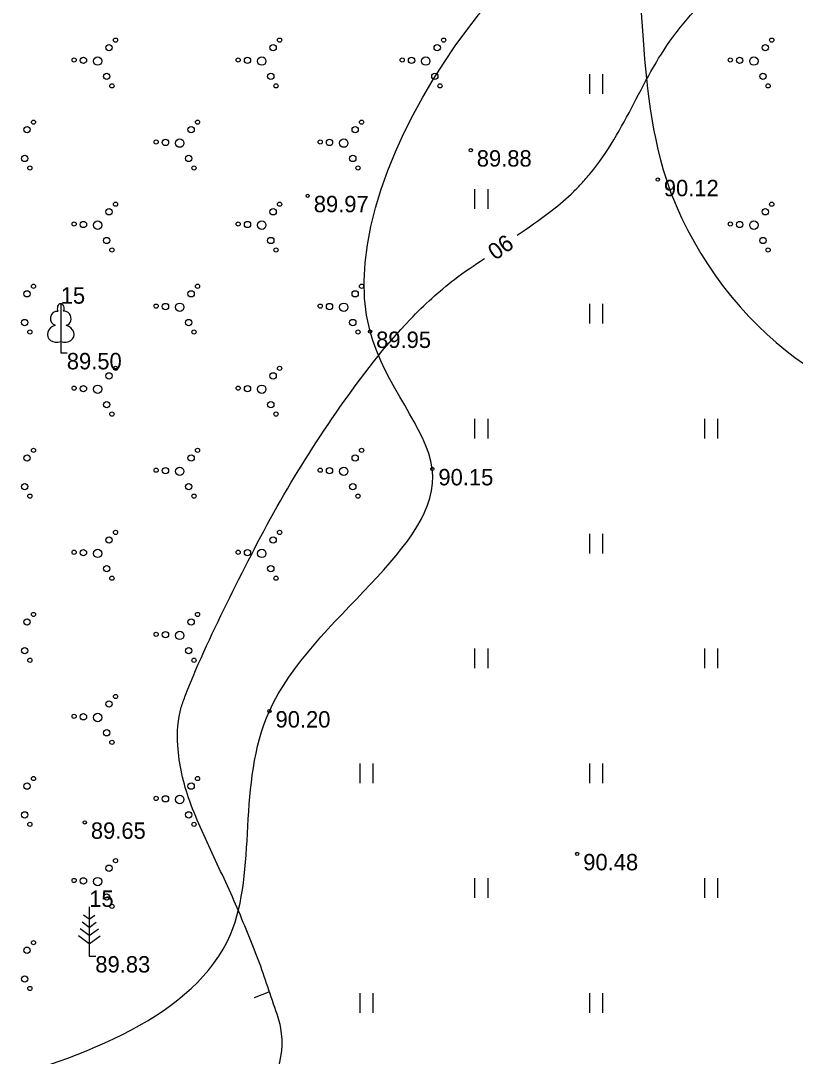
# Model space of a CAD drawing. Extents: x 635228 to 635525, y 248590 to 248800.
# Drawn here: x 635355.15 to 635378.76, y 248677.18 to 248708.73 of the extents above; entities that cross this region are included whole.
import ezdxf

# ---------------------------------------------------------------- set-up
doc = ezdxf.new("R2010")
doc.units = 0
for name, color, linetype in [('RELJ_AATZ_####_TKST_#', 7, 'Continuous'), ('RELJ_ELEM_####_####_#', 7, 'Continuous'), ('RELJ_HORZ_####_TKST_#', 7, 'Continuous'), ('RELJ_HORZ_PAMT_####_#', 7, 'Continuous'), ('RELJ_HORZ_RESN_####_#', 7, 'Continuous'), ('RELJ_NOGA_####_####_#', 7, 'Continuous'), ('RELJ_NOGL_####_####_#', 7, 'Continuous'), ('TERT_DIAM_####_TKST_#', 7, 'Continuous'), ('TERT_ELEM_####_####_#', 7, 'Continuous'), ('TERT_KONT_####_####_#', 7, 'Continuous')]:
    doc.layers.add(name, color=color, linetype=linetype)

msp = doc.modelspace()

# ---------------------------------------------------------------- linework, layer by layer
at = {"layer": 'RELJ_ELEM_####_####_#'}
for centre in [(635368.869, 248704.785), (635374.571, 248703.89), (635363.901, 248703.394), (635365.801, 248699.259), (635367.699, 248695.072), (635362.735, 248687.694), (635357.107, 248684.303), (635372.114, 248683.343)]:
    msp.add_circle(centre, 0.05, dxfattribs=at)
at = {"layer": 'RELJ_HORZ_PAMT_####_#'}
msp.add_spline([(635330.297, 248677.354), (635331.177, 248678.319), (635332.06, 248679.489), (635332.793, 248680.772), (635333.481, 248682.089), (635334.226, 248683.36), (635335.284, 248684.77), (635336.431, 248686.125), (635337.538, 248687.508), (635338.035, 248688.237), (635338.472, 248689.004), (635339.583, 248691.554), (635340.487, 248694.188), (635341.335, 248696.84), (635341.787, 248698.153), (635342.281, 248699.447), (635343.206, 248701.423), (635344.222, 248703.369), (635345.157, 248705.345), (635345.54, 248706.364), (635345.837, 248707.412), (635346.445, 248710.352), (635346.944, 248713.307), (635347.835, 248719.233), (635348.116, 248721.113), (635348.378, 248722.995), (635348.645, 248724.878), (635348.937, 248726.758), (635349.503, 248728.159), (635350.332, 248729.539), (635351.235, 248730.852), (635351.672, 248731.412), (635352.153, 248731.934), (635352.67, 248732.415), (635353.216, 248732.849), (635353.585, 248732.808), (635353.973, 248732.393), (635354.375, 248731.871), (635354.581, 248731.654), (635354.79, 248731.511), (635355.514, 248731.162), (635356.357, 248730.815), (635357.156, 248730.69), (635357.748, 248731.008), (635358.207, 248731.666), (635358.657, 248732.33), (635359.531, 248733.675), (635361.193, 248736.42), (635362.771, 248739.216), (635364.301, 248742.038), (635372.089, 248756.526)], degree=3, dxfattribs=at)
at = {"layer": 'RELJ_HORZ_RESN_####_#'}
msp.add_line((635362.735, 248679.142), (635362.27, 248678.96), dxfattribs=at)
for points in [[(635370.286, 248702.191), (635371.268, 248702.893), (635371.931, 248703.448), (635372.235, 248703.758), (635372.523, 248704.086), (635373.233, 248705.103), (635373.842, 248706.207), (635374.44, 248707.318), (635375.119, 248708.351), (635375.519, 248708.837), (635375.945, 248709.297), (635376.871, 248710.138), (635378.872, 248711.708), (635380.875, 248713.355), (635381.799, 248714.3), (635382.631, 248715.376), (635384.271, 248718.308), (635385.412, 248721.331), (635386.184, 248724.417), (635386.472, 248725.973), (635386.718, 248727.534), (635386.765, 248728.402), (635386.702, 248729.274), (635386.549, 248730.144), (635386.323, 248731.007), (635386.319, 248731.019)], [(635342.967, 248665.189), (635350.649, 248671.097), (635353.044, 248672.199), (635354.147, 248672.641), (635355.27, 248673.022), (635357.544, 248673.711), (635360.916, 248674.993), (635361.461, 248675.281), (635362, 248675.6), (635362.585, 248676.091), (635362.941, 248676.666), (635363.082, 248678.034), (635362.825, 248678.873), (635362.542, 248679.71), (635361.896, 248681.359), (635361.504, 248682.258), (635361.094, 248683.142), (635360.687, 248684.033), (635360.306, 248684.949), (635359.942, 248686.647), (635360.049, 248687.813), (635360.176, 248688.176), (635361.529, 248691.159), (635363.072, 248694.104), (635364.881, 248696.95), (635367.032, 248699.635), (635368.378, 248700.848), (635369.286, 248701.486)]]:
    msp.add_spline(points, degree=3, dxfattribs=at)
at = {"layer": 'RELJ_NOGA_####_####_#'}
for points in [[(635375.27, 248754.857), (635369.314, 248744.971), (635367.429, 248741.507), (635365.696, 248737.957), (635363.943, 248734.417), (635363.006, 248732.681), (635362, 248730.984), (635361.355, 248730.103), (635360.628, 248729.283), (635359.885, 248728.474), (635359.193, 248727.625), (635357.58, 248725.368), (635356.018, 248723.079), (635353.089, 248718.349), (635349.569, 248710.638), (635349.163, 248709.221), (635348.864, 248707.772), (635348.539, 248706.335), (635348.053, 248704.954), (635343.12, 248694.162), (635337.407, 248681.667), (635331.093, 248670.147), (635326.8, 248663.851)], [(635326.8, 248663.851), (635325.31, 248661.345), (635325.174, 248660.918), (635325.219, 248660.451), (635325.416, 248659.984), (635325.736, 248659.553), (635326.126, 248659.27), (635326.575, 248659.146), (635327.409, 248659.333), (635327.907, 248659.688), (635328.397, 248660.078), (635328.864, 248660.506), (635329.288, 248660.978), (635331.594, 248663.918), (635332.687, 248665.412), (635333.734, 248666.95), (635337.875, 248673.353), (635341.554, 248680.001), (635347.428, 248693.006), (635353.063, 248706.101), (635354.098, 248708.621), (635355.097, 248711.155), (635356.117, 248713.682), (635356.653, 248714.935), (635357.216, 248716.179), (635358.916, 248719.218), (635360.822, 248722.14), (635362.339, 248724.363), (635363.916, 248726.545), (635365.467, 248728.744), (635366.906, 248731.015), (635368.464, 248733.981), (635369.863, 248737.03), (635371.249, 248740.086), (635372.769, 248743.072), (635378.435, 248753.196)]]:
    msp.add_spline(points, degree=3, dxfattribs=at)
at = {"layer": 'RELJ_NOGL_####_####_#'}
msp.add_spline([(635326.936, 248660.713), (635331.766, 248667.928), (635333.88, 248671.254), (635335.853, 248674.668), (635337.706, 248678.153), (635339.464, 248681.691), (635342.12, 248687.391), (635344.65, 248693.14), (635347.108, 248698.916), (635349.548, 248704.698), (635350.777, 248707.84), (635351.91, 248711.022), (635353.067, 248714.195), (635353.692, 248715.764), (635354.368, 248717.312), (635355.034, 248718.536), (635355.835, 248719.677), (635357.677, 248721.811), (635359.567, 248723.919), (635361.176, 248726.206), (635362.355, 248728.434), (635362.939, 248729.551), (635363.546, 248730.656), (635367.422, 248737.348), (635371.307, 248744.035), (635372.506, 248746.487), (635373.579, 248749.023), (635374.785, 248751.459), (635376.384, 248753.612), (635376.807, 248754.05)], degree=3, dxfattribs=at)
at = {"layer": 'TERT_ELEM_####_####_#'}
for p, q in [((635372.5, 248706.5), (635372.5, 248707.1)), ((635372.9, 248706.5), (635372.9, 248707.1)), ((635369, 248703), (635369, 248703.6)), ((635369.4, 248703), (635369.4, 248703.6)), ((635372.5, 248699.5), (635372.5, 248700.1)), ((635372.9, 248699.5), (635372.9, 248700.1)), ((635356.374, 248698.954), (635356.374, 248698.607)), ((635356.374, 248698.607), (635356.574, 248698.607)), ((635369, 248696), (635369, 248696.6)), ((635369.4, 248696), (635369.4, 248696.6)), ((635376, 248696), (635376, 248696.6)), ((635376.4, 248696), (635376.4, 248696.6)), ((635372.5, 248692.5), (635372.5, 248693.1)), ((635372.9, 248692.5), (635372.9, 248693.1)), ((635369, 248689), (635369, 248689.6)), ((635369.4, 248689), (635369.4, 248689.6)), ((635376, 248689), (635376, 248689.6)), ((635376.4, 248689), (635376.4, 248689.6)), ((635365.5, 248685.5), (635365.5, 248686.1)), ((635365.9, 248685.5), (635365.9, 248686.1)), ((635372.5, 248685.5), (635372.5, 248686.1)), ((635372.9, 248685.5), (635372.9, 248686.1)), ((635369, 248682), (635369, 248682.6)), ((635369.4, 248682), (635369.4, 248682.6)), ((635376, 248682), (635376, 248682.6)), ((635376.4, 248682), (635376.4, 248682.6)), ((635357.243, 248681.353), (635357.067, 248681.481)), ((635357.243, 248681.729), (635357.243, 248680.229)), ((635357.243, 248681.353), (635357.417, 248681.481)), ((635357.243, 248681.103), (635357.027, 248681.261)), ((635357.243, 248681.103), (635357.459, 248681.261)), ((635357.243, 248680.603), (635356.911, 248680.847)), ((635357.243, 248680.853), (635356.965, 248681.057)), ((635357.243, 248680.853), (635357.521, 248681.057)), ((635357.243, 248680.603), (635357.577, 248680.847)), ((635357.243, 248680.229), (635357.443, 248680.229)), ((635365.5, 248678.5), (635365.5, 248679.1)), ((635365.9, 248678.5), (635365.9, 248679.1)), ((635372.5, 248678.5), (635372.5, 248679.1)), ((635372.9, 248678.5), (635372.9, 248679.1))]:
    msp.add_line(p, q, dxfattribs=at)
for points in [[(635356.374, 248700.107), (635356.374, 248698.954)], [(635356.464, 248699.875), (635356.463, 248699.876)]]:
    msp.add_lwpolyline(points, dxfattribs=at)
for centre, radius in [((635357.848, 248707.908), 0.096), ((635358.044, 248708.139), 0.064), ((635362.848, 248707.908), 0.096), ((635363.044, 248708.139), 0.064), ((635367.848, 248707.908), 0.096), ((635368.044, 248708.139), 0.064), ((635377.848, 248707.908), 0.096), ((635378.044, 248708.139), 0.064), ((635357.5, 248707.5), 0.128), ((635362.5, 248707.5), 0.128), ((635367.5, 248707.5), 0.128), ((635377.5, 248707.5), 0.128), ((635356.782, 248707.534), 0.064), ((635357.066, 248707.521), 0.096), ((635361.782, 248707.534), 0.064), ((635362.066, 248707.521), 0.096), ((635366.782, 248707.534), 0.064), ((635367.066, 248707.521), 0.096), ((635376.782, 248707.534), 0.064), ((635377.066, 248707.521), 0.096), ((635357.776, 248707.033), 0.096), ((635362.776, 248707.033), 0.096), ((635367.776, 248707.033), 0.096), ((635377.776, 248707.033), 0.096), ((635357.934, 248706.744), 0.064), ((635362.934, 248706.744), 0.064), ((635367.934, 248706.744), 0.064), ((635377.934, 248706.744), 0.064), ((635355.348, 248705.408), 0.096), ((635355.544, 248705.639), 0.064), ((635360.348, 248705.408), 0.096), ((635360.544, 248705.639), 0.064), ((635365.348, 248705.408), 0.096), ((635365.544, 248705.639), 0.064), ((635359.566, 248705.021), 0.096), ((635360, 248705), 0.128), ((635364.566, 248705.021), 0.096), ((635365, 248705), 0.128), ((635359.282, 248705.034), 0.064), ((635364.282, 248705.034), 0.064), ((635355.276, 248704.533), 0.096), ((635360.276, 248704.533), 0.096), ((635365.276, 248704.533), 0.096), ((635355.434, 248704.244), 0.064), ((635360.434, 248704.244), 0.064), ((635365.434, 248704.244), 0.064), ((635357.848, 248702.908), 0.096), ((635358.044, 248703.139), 0.064), ((635362.848, 248702.908), 0.096), ((635363.044, 248703.139), 0.064), ((635377.848, 248702.908), 0.096), ((635378.044, 248703.139), 0.064), ((635356.782, 248702.534), 0.064), ((635357.066, 248702.521), 0.096), ((635357.5, 248702.5), 0.128), ((635361.782, 248702.534), 0.064), ((635362.066, 248702.521), 0.096), ((635362.5, 248702.5), 0.128), ((635376.782, 248702.534), 0.064), ((635377.066, 248702.521), 0.096), ((635377.5, 248702.5), 0.128), ((635357.776, 248702.033), 0.096), ((635362.776, 248702.033), 0.096), ((635377.776, 248702.033), 0.096), ((635357.934, 248701.744), 0.064), ((635362.934, 248701.744), 0.064), ((635377.934, 248701.744), 0.064), ((635355.544, 248700.639), 0.064), ((635360.544, 248700.639), 0.064), ((635365.544, 248700.639), 0.064), ((635355.348, 248700.408), 0.096), ((635360.348, 248700.408), 0.096), ((635365.348, 248700.408), 0.096), ((635359.282, 248700.034), 0.064), ((635359.566, 248700.021), 0.096), ((635360, 248700), 0.128), ((635364.282, 248700.034), 0.064), ((635364.566, 248700.021), 0.096), ((635365, 248700), 0.128), ((635355.276, 248699.533), 0.096), ((635360.276, 248699.533), 0.096), ((635365.276, 248699.533), 0.096), ((635355.434, 248699.244), 0.064), ((635360.434, 248699.244), 0.064), ((635365.434, 248699.244), 0.064), ((635358.044, 248698.139), 0.064), ((635363.044, 248698.139), 0.064), ((635357.848, 248697.908), 0.096), ((635362.848, 248697.908), 0.096), ((635356.782, 248697.534), 0.064), ((635357.066, 248697.521), 0.096), ((635357.5, 248697.5), 0.128), ((635361.782, 248697.534), 0.064), ((635362.066, 248697.521), 0.096), ((635362.5, 248697.5), 0.128), ((635357.776, 248697.033), 0.096), ((635362.776, 248697.033), 0.096), ((635357.934, 248696.744), 0.064), ((635362.934, 248696.744), 0.064), ((635355.544, 248695.639), 0.064), ((635360.544, 248695.639), 0.064), ((635365.544, 248695.639), 0.064), ((635355.348, 248695.408), 0.096), ((635360.348, 248695.408), 0.096), ((635365.348, 248695.408), 0.096), ((635359.282, 248695.034), 0.064), ((635359.566, 248695.021), 0.096), ((635360, 248695), 0.128), ((635364.282, 248695.034), 0.064), ((635364.566, 248695.021), 0.096), ((635365, 248695), 0.128), ((635355.276, 248694.533), 0.096), ((635360.276, 248694.533), 0.096), ((635365.276, 248694.533), 0.096), ((635355.434, 248694.244), 0.064), ((635360.434, 248694.244), 0.064), ((635365.434, 248694.244), 0.064), ((635358.044, 248693.139), 0.064), ((635363.044, 248693.139), 0.064), ((635357.848, 248692.908), 0.096), ((635362.848, 248692.908), 0.096), ((635356.782, 248692.534), 0.064), ((635357.066, 248692.521), 0.096), ((635357.5, 248692.5), 0.128), ((635361.782, 248692.534), 0.064), ((635362.066, 248692.521), 0.096), ((635362.5, 248692.5), 0.128), ((635357.776, 248692.033), 0.096), ((635362.776, 248692.033), 0.096), ((635357.934, 248691.744), 0.064), ((635362.934, 248691.744), 0.064), ((635355.544, 248690.639), 0.064), ((635360.544, 248690.639), 0.064), ((635355.348, 248690.408), 0.096), ((635360.348, 248690.408), 0.096), ((635359.282, 248690.034), 0.064), ((635359.566, 248690.021), 0.096), ((635360, 248690), 0.128), ((635355.276, 248689.533), 0.096), ((635360.276, 248689.533), 0.096), ((635355.434, 248689.244), 0.064), ((635360.434, 248689.244), 0.064), ((635358.044, 248688.139), 0.064), ((635357.848, 248687.908), 0.096), ((635356.782, 248687.534), 0.064), ((635357.066, 248687.521), 0.096), ((635357.5, 248687.5), 0.128), ((635357.776, 248687.033), 0.096), ((635357.934, 248686.744), 0.064), ((635355.544, 248685.639), 0.064), ((635360.544, 248685.639), 0.064), ((635355.348, 248685.408), 0.096), ((635360.348, 248685.408), 0.096), ((635359.282, 248685.034), 0.064), ((635359.566, 248685.021), 0.096), ((635360, 248685), 0.128), ((635355.276, 248684.533), 0.096), ((635360.276, 248684.533), 0.096), ((635355.434, 248684.244), 0.064), ((635360.434, 248684.244), 0.064), ((635358.044, 248683.139), 0.064), ((635357.848, 248682.908), 0.096), ((635356.782, 248682.534), 0.064), ((635357.066, 248682.521), 0.096), ((635357.5, 248682.5), 0.128), ((635357.776, 248682.033), 0.096), ((635357.934, 248681.744), 0.064), ((635355.348, 248680.408), 0.096), ((635355.544, 248680.639), 0.064), ((635355.276, 248679.533), 0.096), ((635355.434, 248679.244), 0.064)]:
    msp.add_circle(centre, radius, dxfattribs=at)
for centre, major_axis, ratio, start_param, end_param in [((635356.374, 248699.957), (0, -0.15), 0.707107, 3.14537, 5.287485), ((635356.374, 248699.957), (0, -0.15), 0.707107, 0.995701, 3.137816), ((635356.246, 248699.662), (-0.039, -0.212), 0.861323, 3.141593, 6.283185), ((635356.502, 248699.662), (0.039, -0.212), 0.861323, 0, 3.141593), ((635356.284, 248699.2), (0.307, 0.095), 0.814445, 1.570796, 4.752015), ((635356.464, 248699.2), (-0.307, 0.095), 0.814445, 1.531171, 4.712389)]:
    msp.add_ellipse(centre, major_axis=major_axis, ratio=ratio, start_param=start_param, end_param=end_param, dxfattribs=at)
at = {"layer": 'TERT_KONT_####_####_#'}
msp.add_spline([(635347.944, 248675.14), (635353.969, 248676.317), (635361.548, 248680.892), (635362.735, 248687.694), (635367.699, 248695.072), (635365.801, 248699.259), (635373.4, 248711.674), (635374.835, 248703.881), (635382.868, 248697.463), (635386.085, 248703.415)], degree=3, dxfattribs=at)

# ---------------------------------------------------------------- texts
at = {"layer": 'RELJ_AATZ_####_TKST_#'}
for s, p in [(' 89.88', (635368.869, 248704.285)), (' 90.12', (635374.569, 248703.381)), (' 89.97', (635363.901, 248702.894)), (' 89.95', (635365.801, 248698.759)), (' 89.50', (635356.374, 248698.107)), (' 90.15', (635367.699, 248694.572)), (' 90.20', (635362.735, 248687.194)), (' 89.65', (635357.107, 248683.803)), (' 90.48', (635372.114, 248682.843)), (' 89.83', (635357.243, 248679.729))]:
    msp.add_text(s, height=0.5, dxfattribs=at).set_placement(p)
at = {"layer": 'RELJ_HORZ_####_TKST_#'}
msp.add_text('90', height=0.5, rotation=215.2316, dxfattribs=at).set_placement((635369.938, 248702.25))
at = {"layer": 'TERT_DIAM_####_TKST_#'}
for p in [(635356.374, 248700.107), (635357.243, 248681.729)]:
    msp.add_text('15', height=0.5, dxfattribs=at).set_placement(p)

doc.saveas('drawing.dxf')
